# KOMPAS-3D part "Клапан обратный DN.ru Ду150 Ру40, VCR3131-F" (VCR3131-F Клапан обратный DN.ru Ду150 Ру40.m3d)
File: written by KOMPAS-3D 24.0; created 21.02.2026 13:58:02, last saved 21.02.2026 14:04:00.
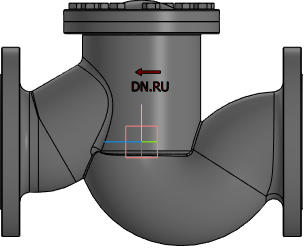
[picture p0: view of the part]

Document properties: Автор: R2D2; Полное имя файла: VCR3131-F Клапан обратный DN.ru Ду150 Ру40.cdw

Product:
- Part/product: Клапан обратный DN.ru Ду150 Ру40  | designation VCR3131-F
    Масса: 53.5
    Раздел спецификации: Прочие изделия
    Форматы листов документа: A2
    Примечание: D100-04046
    additional columns: D100-04046

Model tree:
1. Операция без истории:1

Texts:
  VCR3131-F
